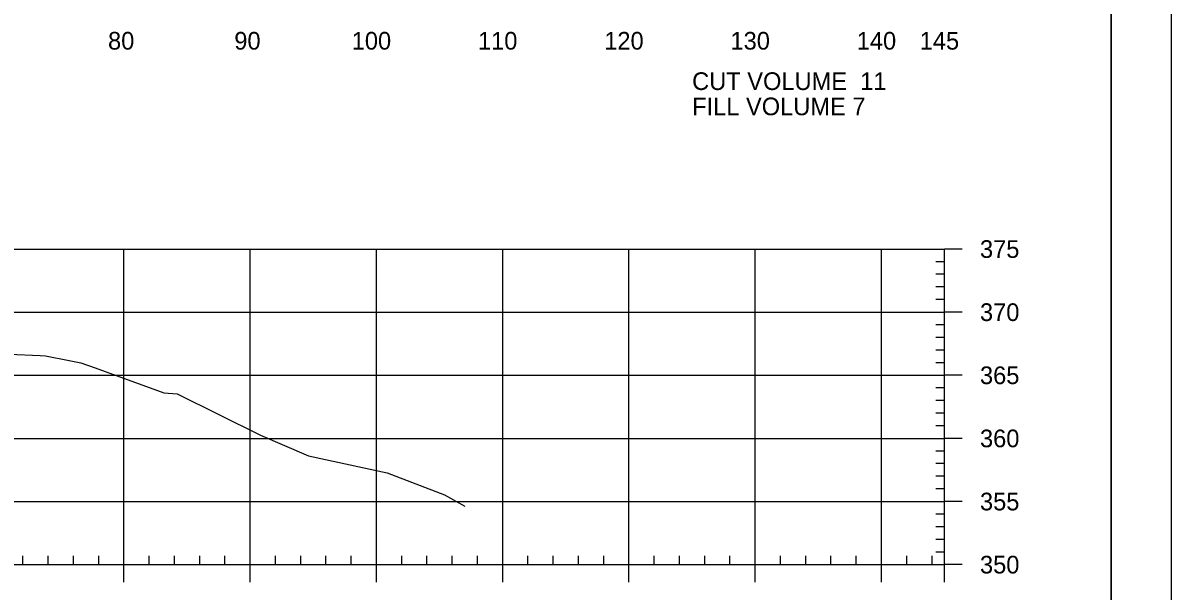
# Model space of a CAD drawing. Extents: x 1359801 to 1362404, y 372415 to 374228.
# Drawn here: x 1360043.4 to 1360134.3, y 372629.2 to 372674.2 of the extents above; entities that cross this region are included whole.
import ezdxf

# ---------------------------------------------------------------- set-up
doc = ezdxf.new("R2010")
doc.units = 0
for name, color, linetype in [('S_DRG_PT_SYM', 7, 'Continuous'), ('S_MAILBOX', 7, 'Continuous'), ('S_PRIMARY_CTL', 7, 'Continuous'), ('S_SHOULDER', 7, 'Continuous'), ('S_UTL_PT_SYM', 7, 'Continuous'), ('S_WATER_UTILITIES', 7, 'Continuous')]:
    doc.layers.add(name, color=color, linetype=linetype)

msp = doc.modelspace()

# ---------------------------------------------------------------- linework, layer by layer
at = {"layer": 'S_DRG_PT_SYM'}
msp.add_lwpolyline([(1360042.251, 372647.927), (1360044.711, 372647.818), (1360045.125, 372647.799), (1360047.014, 372647.419), (1360047.931, 372647.242), (1360049.077, 372646.826), (1360054.516, 372644.856), (1360055.565, 372644.77), (1360062.171, 372641.505), (1360065.975, 372639.859), (1360072.196, 372638.526), (1360076.727, 372636.766), (1360078.347, 372635.876)], dxfattribs=at)
at = {"layer": 'S_MAILBOX'}
for p, q in [((1359826.35, 372656.246), (1360116.35, 372656.246)), ((1360051.35, 372631.246), (1360051.35, 372656.246)), ((1360061.35, 372631.246), (1360061.35, 372656.246)), ((1360071.35, 372631.246), (1360071.35, 372656.246)), ((1360081.35, 372631.246), (1360081.35, 372656.246)), ((1360091.35, 372631.246), (1360091.35, 372656.246)), ((1360101.35, 372631.246), (1360101.35, 372656.246)), ((1360111.35, 372631.246), (1360111.35, 372656.246)), ((1360116.35, 372631.246), (1360116.35, 372656.246)), ((1359826.35, 372651.246), (1360116.35, 372651.246)), ((1359826.35, 372646.246), (1360116.35, 372646.246)), ((1359826.35, 372641.246), (1360116.35, 372641.246)), ((1359826.35, 372636.246), (1360116.35, 372636.246)), ((1359826.35, 372631.246), (1360116.35, 372631.246)), ((1359826.35, 372631.246), (1360116.35, 372631.246))]:
    msp.add_line(p, q, dxfattribs=at)
at = {"layer": 'S_SHOULDER'}
for points in [[(1359800.943, 372734.6), (1360134.283, 372734.6), (1360134.283, 372521.263), (1359800.943, 372521.263)], [(1360047.27, 372730.706), (1360047.27, 372720.826), (1360083.002, 372720.826), (1360083.002, 372717.906), (1360106.202, 372717.906), (1360106.202, 372693.573), (1360129.53, 372693.573), (1360129.53, 372525.246), (1359813.35, 372525.246), (1359813.35, 372730.706)]]:
    msp.add_lwpolyline(points, close=True, dxfattribs=at)
at = {"layer": 'S_UTL_PT_SYM'}
msp.add_line((1360129.53, 372525.246), (1360129.53, 372730.706), dxfattribs=at)
at = {"layer": 'S_WATER_UTILITIES'}
for p, q in [((1360116.35, 372631.246), (1360116.35, 372656.246)), ((1360117.75, 372656.246), (1360116.35, 372656.246)), ((1360116.35, 372655.246), (1360115.65, 372655.246)), ((1360116.35, 372654.246), (1360115.65, 372654.246)), ((1360116.35, 372653.246), (1360115.65, 372653.246)), ((1360116.35, 372652.246), (1360115.65, 372652.246)), ((1360117.75, 372651.246), (1360116.35, 372651.246)), ((1360116.35, 372650.246), (1360115.65, 372650.246)), ((1360116.35, 372649.246), (1360115.65, 372649.246)), ((1360116.35, 372648.246), (1360115.65, 372648.246)), ((1360116.35, 372647.246), (1360115.65, 372647.246)), ((1360117.75, 372646.246), (1360116.35, 372646.246)), ((1360116.35, 372645.246), (1360115.65, 372645.246)), ((1360116.35, 372644.246), (1360115.65, 372644.246)), ((1360116.35, 372643.246), (1360115.65, 372643.246)), ((1360116.35, 372642.246), (1360115.65, 372642.246)), ((1360117.75, 372641.246), (1360116.35, 372641.246)), ((1360116.35, 372640.246), (1360115.65, 372640.246)), ((1360116.35, 372639.246), (1360115.65, 372639.246)), ((1360116.35, 372638.246), (1360115.65, 372638.246)), ((1360116.35, 372637.246), (1360115.65, 372637.246)), ((1360117.75, 372636.246), (1360116.35, 372636.246)), ((1360116.35, 372635.246), (1360115.65, 372635.246)), ((1360116.35, 372634.246), (1360115.65, 372634.246)), ((1360116.35, 372633.246), (1360115.65, 372633.246)), ((1360043.35, 372631.246), (1360043.35, 372631.946)), ((1360045.35, 372631.246), (1360045.35, 372631.946)), ((1360047.35, 372631.246), (1360047.35, 372631.946)), ((1360049.35, 372631.246), (1360049.35, 372631.946)), ((1360053.35, 372631.246), (1360053.35, 372631.946)), ((1360055.35, 372631.246), (1360055.35, 372631.946)), ((1360057.35, 372631.246), (1360057.35, 372631.946)), ((1360059.35, 372631.246), (1360059.35, 372631.946)), ((1360063.35, 372631.246), (1360063.35, 372631.946)), ((1360065.35, 372631.246), (1360065.35, 372631.946)), ((1360067.35, 372631.246), (1360067.35, 372631.946)), ((1360069.35, 372631.246), (1360069.35, 372631.946)), ((1360073.35, 372631.246), (1360073.35, 372631.946)), ((1360075.35, 372631.246), (1360075.35, 372631.946)), ((1360077.35, 372631.246), (1360077.35, 372631.946)), ((1360079.35, 372631.246), (1360079.35, 372631.946)), ((1360083.35, 372631.246), (1360083.35, 372631.946)), ((1360085.35, 372631.246), (1360085.35, 372631.946)), ((1360087.35, 372631.246), (1360087.35, 372631.946)), ((1360089.35, 372631.246), (1360089.35, 372631.946)), ((1360093.35, 372631.246), (1360093.35, 372631.946)), ((1360095.35, 372631.246), (1360095.35, 372631.946)), ((1360097.35, 372631.246), (1360097.35, 372631.946)), ((1360099.35, 372631.246), (1360099.35, 372631.946)), ((1360103.35, 372631.246), (1360103.35, 372631.946)), ((1360105.35, 372631.246), (1360105.35, 372631.946)), ((1360107.35, 372631.246), (1360107.35, 372631.946)), ((1360109.35, 372631.246), (1360109.35, 372631.946)), ((1360113.35, 372631.246), (1360113.35, 372631.946)), ((1360115.35, 372631.246), (1360115.35, 372631.946)), ((1360116.35, 372632.246), (1360115.65, 372632.246)), ((1359826.35, 372631.246), (1360116.35, 372631.246)), ((1360051.35, 372629.846), (1360051.35, 372631.246)), ((1360061.35, 372629.846), (1360061.35, 372631.246)), ((1360071.35, 372629.846), (1360071.35, 372631.246)), ((1360081.35, 372629.846), (1360081.35, 372631.246)), ((1360091.35, 372629.846), (1360091.35, 372631.246)), ((1360101.35, 372629.846), (1360101.35, 372631.246)), ((1360111.35, 372629.846), (1360111.35, 372631.246)), ((1360116.35, 372629.846), (1360116.35, 372631.246)), ((1360117.75, 372631.246), (1360116.35, 372631.246)), ((1360117.75, 372631.246), (1360116.35, 372631.246))]:
    msp.add_line(p, q, dxfattribs=at)

# ---------------------------------------------------------------- texts
at = {"layer": 'S_PRIMARY_CTL'}
for s, p in [('80', (1360050.089, 372672.045)), ('90', (1360060.089, 372672.045)), ('100', (1360069.389, 372672.045)), ('110', (1360079.389, 372672.045)), ('120', (1360089.389, 372672.045)), ('130', (1360099.389, 372672.045)), ('140', (1360109.389, 372672.045)), ('145', (1360114.376, 372672.045)), ('CUT VOLUME  11', (1360096.35, 372668.845)), ('FILL VOLUME 7', (1360096.35, 372666.845)), ('375', (1360119.15, 372655.546)), ('370', (1360119.15, 372650.546)), ('365', (1360119.15, 372645.546)), ('360', (1360119.15, 372640.546)), ('355', (1360119.15, 372635.546)), ('350', (1360119.15, 372630.546))]:
    msp.add_text(s, height=1.4, dxfattribs=at).set_placement(p)

doc.saveas('drawing.dxf')
